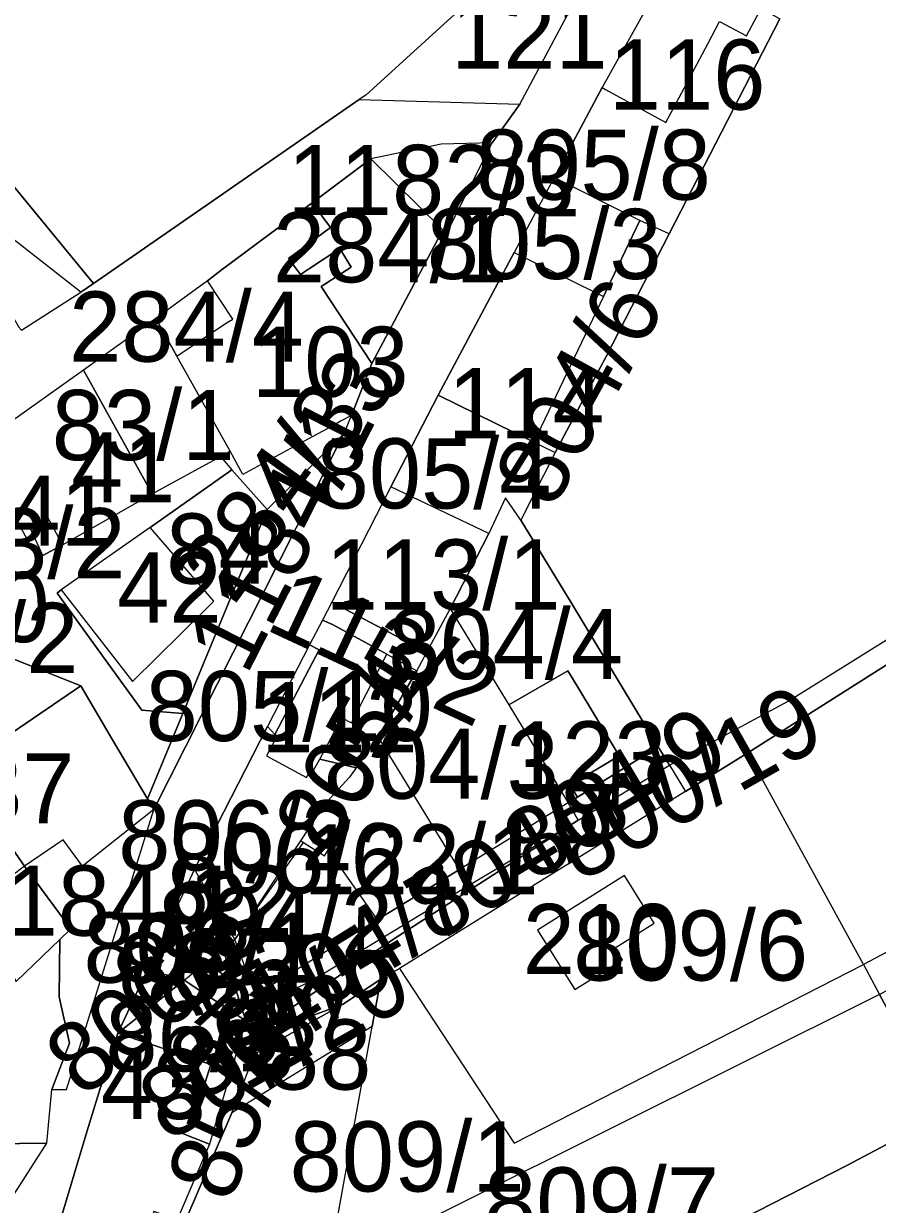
# Model space of a CAD drawing. Extents: x -623250 to -619626, y -1079612 to -1075424.
# Drawn here: x -621368.8 to -621247.2, y -1077081.9 to -1076913.6 of the extents above; entities that cross this region are included whole.
import ezdxf

# ---------------------------------------------------------------- set-up
doc = ezdxf.new("R2010")
doc.units = 0
for name, color, linetype in [('Hranice převzatá (k_ú_Džbánov - vnitřní obvod)', 7, 'Continuous'), ('Hranice šetřená (k_ú_Džbánov - vnitřní obvod)', 7, 'Continuous'), ('Parcela nároku', 7, 'Continuous'), ('Parcelní číslo', 7, 'Continuous')]:
    doc.layers.add(name, color=color, linetype=linetype)

msp = doc.modelspace()

# ---------------------------------------------------------------- linework, layer by layer
at = {"layer": 'Hranice převzatá (k_ú_Džbánov - vnitřní obvod)'}
msp.add_line((-621276.85, -1076943.57), (-621261.07, -1076912.95), dxfattribs=at)
at = {"layer": 'Hranice šetřená (k_ú_Džbánov - vnitřní obvod)'}
for points in [[(-621276.85, -1076943.57), (-621285.83, -1076961.08), (-621293.09, -1076974.77), (-621297.99, -1076984.39), (-621290.77, -1076996.21), (-621278.41, -1077016.7), (-621276.8, -1077019.33), (-621274.52, -1077023.06), (-621265.63, -1077017.55)], [(-621265.63, -1077017.55), (-621210.28, -1076982.43), (-621187.76, -1076968.09), (-621182.95, -1076968.95), (-621180.28, -1076982.79), (-621175.85, -1077005.66), (-621175.29, -1077008.58), (-621176.78, -1077009.37), (-621249.17, -1077047.73), (-621246.87, -1077052), (-621237.68, -1077069.07), (-621251.52, -1077076.38), (-621294, -1077098.09)]]:
    msp.add_lwpolyline(points, dxfattribs=at)
at = {"layer": 'Parcela nároku'}
for points in [[(-621388.91, -1076914.43), (-621261.7, -1076848.72), (-621265.74, -1076862.26), (-621268.27, -1076865.58), (-621302.1, -1076905.64), (-621306.34, -1076911.31), (-621320.09, -1076923.81), (-621321.03, -1076924.46), (-621358.9, -1076950.67), (-621371.51, -1076935.3)], [(-621263.97, -1076911.91), (-621270.87, -1076908.16), (-621270.64, -1076907.72), (-621275.91, -1076904.88), (-621276.33, -1076904.65), (-621286.38, -1076922.74), (-621285.9, -1076923.02), (-621277.33, -1076927.74), (-621271.34, -1076916.49), (-621269.65, -1076913.33), (-621265.81, -1076915.39)], [(-621320.09, -1076923.81), (-621321.03, -1076924.46), (-621298.1, -1076925.1), (-621290.94, -1076911.65), (-621292.93, -1076910.56), (-621301.18, -1076906.02), (-621302.1, -1076905.64), (-621306.34, -1076911.31)], [(-621293.22, -1076935.57), (-621286.38, -1076922.74), (-621285.9, -1076923.02), (-621277.33, -1076927.74), (-621271.34, -1076916.49), (-621269.65, -1076913.33), (-621265.81, -1076915.39), (-621263.97, -1076911.91), (-621270.87, -1076908.16), (-621270.64, -1076907.72), (-621265.64, -1076910.36), (-621261.07, -1076912.95), (-621276.85, -1076943.57), (-621281.03, -1076941.69)], [(-621400.8, -1076920.49), (-621388.91, -1076914.43), (-621371.51, -1076935.3), (-621358.9, -1076950.67), (-621360.7, -1076951.91), (-621382.24, -1076935.03)], [(-621302.09, -1076930.63), (-621309.35, -1076930.8), (-621319.37, -1076932.91), (-621309.08, -1076943.03), (-621308.57, -1076943.53)], [(-621319.37, -1076932.91), (-621309.08, -1076943.03), (-621319.23, -1076962.06), (-621326.44, -1076951.11), (-621322.14, -1076948.34), (-621323.79, -1076945.68), (-621328.08, -1076948.53), (-621329.38, -1076949.38), (-621331.07, -1076947.1), (-621325.12, -1076942.7), (-621327.72, -1076939.17)], [(-621379.74, -1076967.98), (-621381.79, -1076964.51), (-621383.13, -1076965.27), (-621387.85, -1076967.95), (-621390.29, -1076963.84), (-621392.46, -1076965.01), (-621396.79, -1076957.69), (-621394.63, -1076956.52), (-621397.27, -1076952.05), (-621392.43, -1076949.18), (-621385.65, -1076945.85), (-621384.21, -1076945.15), (-621378.08, -1076942.14), (-621369.5, -1076956.9), (-621369.14, -1076957.33), (-621360.7, -1076951.91), (-621382.24, -1076935.03), (-621407.3, -1076948.06), (-621406.33, -1076956.01), (-621402.48, -1076963.6), (-621399.42, -1076969.63), (-621397.07, -1076974.26)], [(-621281.03, -1076941.69), (-621293.22, -1076935.57), (-621298.92, -1076946.24), (-621290.81, -1076950.26), (-621286.98, -1076952.16), (-621286.21, -1076952.54)], [(-621339.91, -1076956.28), (-621339.04, -1076955.74), (-621342.62, -1076950.28), (-621340.68, -1076948.78), (-621333.65, -1076943.52), (-621327.72, -1076939.17), (-621325.12, -1076942.7), (-621331.07, -1076947.1), (-621329.38, -1076949.38), (-621328.08, -1076948.53), (-621323.79, -1076945.68), (-621322.14, -1076948.34), (-621326.44, -1076951.11), (-621319.23, -1076962.06), (-621322.12, -1076969.47), (-621323.57, -1076970.26), (-621324.89, -1076970.98), (-621330.27, -1076973.91), (-621337.59, -1076977.91), (-621339.39, -1076974.58), (-621346.99, -1076961.02)], [(-621276.85, -1076943.57), (-621281.03, -1076941.69), (-621286.21, -1076952.54), (-621296.11, -1076973.28), (-621293.09, -1076974.77), (-621285.83, -1076961.08)], [(-621290.81, -1076950.26), (-621286.98, -1076952.16), (-621286.21, -1076952.54), (-621296.11, -1076973.28), (-621309.78, -1076966.57), (-621298.92, -1076946.24)], [(-621342.62, -1076950.28), (-621350.01, -1076955.67), (-621346.99, -1076961.02), (-621339.91, -1076956.28), (-621339.04, -1076955.74)], [(-621346.99, -1076961.02), (-621350.01, -1076955.67), (-621360.3, -1076963.02), (-621359.65, -1076964.2), (-621350.51, -1076980.67), (-621340.76, -1076975.33), (-621339.39, -1076974.58)], [(-621359.65, -1076964.2), (-621360.3, -1076963.02), (-621374.01, -1076972.77), (-621374.75, -1076973.9), (-621375.15, -1076974.51), (-621366.89, -1076989.84), (-621366.1, -1076989.42), (-621367.97, -1076985.39), (-621365.43, -1076983.95), (-621363.29, -1076987.92), (-621350.51, -1076980.67)], [(-621316.13, -1077044.13), (-621289.81, -1077027.14), (-621276.8, -1077019.33), (-621259.89, -1077010.22), (-621184.11, -1076962.92), (-621183.61, -1076965.53), (-621187.76, -1076968.09), (-621210.28, -1076982.43), (-621265.63, -1077017.55), (-621315.29, -1077048.32), (-621317.95, -1077049.84), (-621323.41, -1077053.43), (-621328.79, -1077055.44), (-621331.46, -1077056.09), (-621334.27, -1077056.32)], [(-621309.78, -1076966.57), (-621296.11, -1076973.28), (-621293.09, -1076974.77), (-621297.99, -1076984.39), (-621300.15, -1076981.22), (-621302.56, -1076986.31), (-621316.49, -1076979.64)], [(-621180.28, -1076982.79), (-621175.85, -1077005.66), (-621175.29, -1077008.58), (-621176.78, -1077009.37), (-621249.17, -1077047.73), (-621265.63, -1077017.55), (-621210.28, -1076982.43), (-621187.76, -1076968.09)], [(-621337.59, -1076977.91), (-621339.39, -1076974.58), (-621340.76, -1076975.33), (-621339.16, -1076977.21), (-621334.11, -1076982.88), (-621323.26, -1076972.15), (-621322.86, -1076971.35), (-621322.12, -1076969.47), (-621323.57, -1076970.26), (-621324.89, -1076970.98), (-621330.27, -1076973.91)], [(-621346.15, -1077011.97), (-621334.11, -1076982.88), (-621323.26, -1076972.15), (-621350.29, -1077025.63), (-621351.18, -1077024.13)], [(-621356.81, -1077002.91), (-621353.34, -1077007.39), (-621346.41, -1077000.56), (-621341.74, -1076995.95), (-621350.8, -1076985.46), (-621339.16, -1076977.21), (-621334.11, -1076982.88), (-621346.15, -1077011.97), (-621351.97, -1077011.5), (-621364.08, -1076994.82), (-621363.47, -1076994.33)], [(-621302.56, -1076986.31), (-621316.49, -1076979.64), (-621324.93, -1076996.07), (-621311.36, -1077003.21), (-621308.04, -1076997.05)], [(-621302.56, -1076986.31), (-621308.04, -1076997.05), (-621299.71, -1077010.73), (-621291.29, -1077005.87), (-621290.67, -1077006.89), (-621287.93, -1077011.41), (-621283.96, -1077017.97), (-621290.94, -1077022.16), (-621289.92, -1077023.88), (-621278.41, -1077016.7), (-621290.77, -1076996.21), (-621297.99, -1076984.39), (-621300.15, -1076981.22)], [(-621367.97, -1076985.39), (-621365.43, -1076983.95), (-621363.29, -1076987.92), (-621366.1, -1076989.42)], [(-621341.74, -1076995.95), (-621350.8, -1076985.46), (-621356.16, -1076989.21), (-621363.47, -1076994.33), (-621356.81, -1077002.91), (-621353.34, -1077007.39), (-621346.41, -1077000.56)], [(-621413.47, -1076991.52), (-621407.45, -1076988.85), (-621401, -1076993.07), (-621390.43, -1076997.35), (-621376.71, -1077001.63), (-621371.16, -1077003.85), (-621360.7, -1077008.03), (-621378.27, -1077020), (-621368.71, -1077033.73), (-621371.16, -1077035.61), (-621399.89, -1076998.58)], [(-621399.89, -1076998.58), (-621413.47, -1076991.52), (-621418.63, -1076993.81), (-621407.49, -1077016.65), (-621409.18, -1077017.58), (-621391.08, -1077055.64), (-621389.91, -1077057.9), (-621374.82, -1077088.56), (-621373.89, -1077088.8), (-621372.14, -1077089.23), (-621370.85, -1077081.53), (-621365.54, -1077073.2), (-621377.33, -1077073.32), (-621386.59, -1077059.95), (-621391.92, -1077049.63), (-621375.37, -1077039.83), (-621369.9, -1077050.16), (-621363.69, -1077044.16), (-621362.12, -1077042.64), (-621368.71, -1077033.73), (-621371.16, -1077035.61)], [(-621324.93, -1076996.07), (-621326.25, -1076998.64), (-621324.83, -1076999.28), (-621317.08, -1077003.52), (-621312.79, -1077005.87), (-621311.36, -1077003.21)], [(-621299.71, -1077010.73), (-621291.22, -1077024.69), (-621306.72, -1077034.21), (-621318.33, -1077015.29), (-621312.79, -1077005.87), (-621311.36, -1077003.21), (-621308.04, -1076997.05)], [(-621327.67, -1077004.7), (-621333.04, -1077014.97), (-621332.72, -1077015.14), (-621334.24, -1077018), (-621328.51, -1077021.1), (-621328.06, -1077020.3), (-621327.76, -1077020.45), (-621326.64, -1077018.46), (-621323.5, -1077012.56), (-621322.13, -1077013.28), (-621318.92, -1077007.07), (-621317.08, -1077003.52), (-621324.83, -1076999.28), (-621326.25, -1076998.64), (-621328.09, -1077002.19), (-621326.74, -1077002.9)], [(-621328.09, -1077002.19), (-621334.09, -1077013.79), (-621333.04, -1077014.97), (-621327.67, -1077004.7), (-621326.74, -1077002.9)], [(-621323.5, -1077012.56), (-621322.13, -1077013.28), (-621318.92, -1077007.07), (-621317.08, -1077003.52), (-621312.79, -1077005.87), (-621318.33, -1077015.29), (-621321.45, -1077019.71), (-621326.64, -1077018.46)], [(-621283.96, -1077017.97), (-621287.93, -1077011.41), (-621290.67, -1077006.89), (-621291.29, -1077005.87), (-621299.71, -1077010.73), (-621291.22, -1077024.69), (-621289.92, -1077023.88), (-621290.94, -1077022.16)], [(-621378.27, -1077020), (-621360.7, -1077008.03), (-621356.16, -1077015.71), (-621351.18, -1077024.13), (-621350.29, -1077025.63), (-621360.47, -1077033.73), (-621363.22, -1077029.96), (-621368.71, -1077033.73)], [(-621176.78, -1077009.37), (-621249.17, -1077047.73), (-621246.87, -1077052), (-621187.87, -1077019.16), (-621177.76, -1077013.49)], [(-621326.64, -1077018.46), (-621321.45, -1077019.71), (-621322.39, -1077021.04), (-621325.99, -1077024.98), (-621329.39, -1077030.08), (-621338.72, -1077044.17), (-621344.48, -1077034.16), (-621334.09, -1077013.79), (-621333.04, -1077014.97), (-621332.72, -1077015.14), (-621334.24, -1077018), (-621328.51, -1077021.1), (-621328.06, -1077020.3), (-621327.76, -1077020.45)], [(-621318.33, -1077015.29), (-621321.45, -1077019.71), (-621322.39, -1077021.04), (-621325.99, -1077024.98), (-621329.39, -1077030.08), (-621328.96, -1077030.35), (-621325.98, -1077032.25), (-621325.43, -1077031.43), (-621318.47, -1077041.37), (-621306.72, -1077034.21)], [(-621265.63, -1077017.55), (-621315.29, -1077048.32), (-621298.91, -1077073.21), (-621249.17, -1077047.73)], [(-621289.92, -1077023.88), (-621291.22, -1077024.69), (-621289.81, -1077027.14), (-621276.8, -1077019.33), (-621278.41, -1077016.7)], [(-621291.22, -1077024.69), (-621306.72, -1077034.21), (-621305.79, -1077036.68), (-621289.81, -1077027.14)], [(-621362.12, -1077042.64), (-621363.69, -1077044.16), (-621363.76, -1077052.36), (-621362.28, -1077058.96), (-621364.82, -1077065.54), (-621362.74, -1077065.56), (-621350.29, -1077025.63), (-621360.47, -1077033.73), (-621363.22, -1077029.96), (-621368.71, -1077033.73)], [(-621305.79, -1077036.68), (-621289.81, -1077027.14), (-621316.13, -1077044.13), (-621334.27, -1077056.32), (-621335.73, -1077052.34), (-621335.81, -1077052.11), (-621331.49, -1077051.5), (-621329.39, -1077050.8), (-621327.42, -1077049.83)], [(-621329.39, -1077030.08), (-621338.72, -1077044.17), (-621328.96, -1077030.35)], [(-621328.96, -1077030.35), (-621325.98, -1077032.25), (-621325.43, -1077031.43), (-621318.47, -1077041.37), (-621335.81, -1077052.11), (-621338.72, -1077044.17)], [(-621338.72, -1077044.17), (-621344.48, -1077034.16), (-621351.33, -1077048.78), (-621346.81, -1077049.41), (-621345.97, -1077049.96), (-621342.62, -1077047.26), (-621340.44, -1077045.54)], [(-621306.72, -1077034.21), (-621318.47, -1077041.37), (-621335.81, -1077052.11), (-621331.49, -1077051.5), (-621329.39, -1077050.8), (-621327.42, -1077049.83), (-621305.79, -1077036.68)], [(-621295.61, -1077042.83), (-621290.29, -1077051.31), (-621283.48, -1077047.08), (-621284.52, -1077045.37), (-621278.97, -1077041.85), (-621283.22, -1077035.04)], [(-621283.22, -1077035.04), (-621295.61, -1077042.83), (-621290.29, -1077051.31), (-621283.48, -1077047.08), (-621284.52, -1077045.37), (-621278.97, -1077041.85)], [(-621362.28, -1077058.96), (-621363.76, -1077052.36), (-621363.69, -1077044.16), (-621369.9, -1077050.16), (-621375.37, -1077039.83), (-621391.92, -1077049.63), (-621386.59, -1077059.95), (-621377.33, -1077073.32), (-621365.54, -1077073.2), (-621364.82, -1077065.54)], [(-621335.81, -1077052.11), (-621338.72, -1077044.17), (-621340.44, -1077045.54), (-621338.86, -1077050.46), (-621337.53, -1077051.55), (-621336.66, -1077052.06), (-621335.73, -1077052.34)], [(-621342.62, -1077047.26), (-621340.44, -1077045.54), (-621338.86, -1077050.46), (-621341.91, -1077047.96)], [(-621341.91, -1077047.96), (-621338.86, -1077050.46), (-621337.16, -1077055.74), (-621345.97, -1077049.96), (-621342.62, -1077047.26)], [(-621251.52, -1077076.38), (-621237.68, -1077069.07), (-621195.75, -1077048.12), (-621213.24, -1077089.84), (-621248.89, -1077106.94), (-621280.89, -1077123.84), (-621283.01, -1077121.21), (-621310.49, -1077133.23), (-621335.24, -1077144.05), (-621334, -1077138.41), (-621331.64, -1077139.45), (-621320.19, -1077112.66), (-621294, -1077098.09)], [(-621298.91, -1077073.21), (-621249.17, -1077047.73), (-621246.87, -1077052), (-621325.45, -1077091.18), (-621319.17, -1077056.56), (-621317.95, -1077049.84), (-621315.29, -1077048.32)], [(-621346.81, -1077049.41), (-621345.97, -1077049.96), (-621355.43, -1077057.52), (-621351.33, -1077048.78)], [(-621345.97, -1077049.96), (-621337.16, -1077055.74), (-621342.37, -1077073.32), (-621349.19, -1077070.65), (-621348.45, -1077068.57), (-621344.65, -1077069.83), (-621342.15, -1077061.97), (-621355.43, -1077057.52)], [(-621323.41, -1077053.43), (-621317.95, -1077049.84), (-621319.17, -1077056.56), (-621339.15, -1077068.87), (-621335.88, -1077060.47)], [(-621336.66, -1077052.06), (-621335.73, -1077052.34), (-621334.27, -1077056.32), (-621337.16, -1077055.74), (-621338.86, -1077050.46), (-621337.53, -1077051.55)], [(-621328.79, -1077055.44), (-621323.41, -1077053.43), (-621335.88, -1077060.47), (-621334.27, -1077056.32), (-621331.46, -1077056.09)], [(-621246.87, -1077052), (-621325.45, -1077091.18), (-621328.14, -1077111.81), (-621329.46, -1077117.82), (-621320.19, -1077112.66), (-621294, -1077098.09), (-621251.52, -1077076.38), (-621237.68, -1077069.07)], [(-621339.15, -1077068.87), (-621345.88, -1077084.47), (-621353.66, -1077102.52), (-621334.97, -1077109.37), (-621328.14, -1077111.81), (-621325.45, -1077091.18), (-621319.17, -1077056.56)], [(-621337.16, -1077055.74), (-621342.37, -1077073.32), (-621346.97, -1077084.1), (-621345.88, -1077084.47), (-621339.15, -1077068.87), (-621335.88, -1077060.47), (-621334.27, -1077056.32)], [(-621359.83, -1077071.59), (-621357.91, -1077065.42), (-621355.43, -1077057.52), (-621342.15, -1077061.97), (-621344.65, -1077069.83), (-621348.45, -1077068.57), (-621349.19, -1077070.65), (-621342.37, -1077073.32), (-621346.97, -1077084.1), (-621350.29, -1077082.92), (-621352.02, -1077087.69), (-621362.11, -1077084.13), (-621363.46, -1077083.65)]]:
    msp.add_lwpolyline(points, close=True, dxfattribs=at)
for points in [[(-621261.07, -1076912.95), (-621276.85, -1076943.57), (-621285.83, -1076961.08), (-621293.09, -1076974.77), (-621297.99, -1076984.39), (-621290.77, -1076996.21), (-621278.41, -1077016.7), (-621276.8, -1077019.33), (-621259.89, -1077010.22), (-621184.11, -1076962.92), (-621136.45, -1076933.16), (-621132.46, -1076928.18), (-621119.89, -1076900.74)], [(-621276.33, -1076904.65), (-621286.38, -1076922.74), (-621293.22, -1076935.57), (-621298.92, -1076946.24), (-621309.78, -1076966.57), (-621316.49, -1076979.64), (-621324.93, -1076996.07), (-621326.25, -1076998.64), (-621328.09, -1077002.19), (-621334.09, -1077013.79), (-621344.48, -1077034.16), (-621351.33, -1077048.78), (-621355.43, -1077057.52), (-621357.91, -1077065.42), (-621359.83, -1077071.59), (-621363.46, -1077083.65), (-621362.11, -1077084.13), (-621362.86, -1077089.41), (-621364.18, -1077098.66), (-621380.94, -1077143.37), (-621383.09, -1077146.69), (-621409.34, -1077186.93), (-621429.78, -1077218.32)], [(-621432.3, -1077203.73), (-621404.2, -1077162.3), (-621400.21, -1077156.98), (-621391.61, -1077145.5), (-621390.49, -1077143.5), (-621383.83, -1077133.32), (-621376.62, -1077119.92), (-621377.43, -1077118.16), (-621374.04, -1077099.65), (-621372.14, -1077089.23), (-621370.85, -1077081.53), (-621365.54, -1077073.2), (-621364.82, -1077065.54), (-621362.74, -1077065.56), (-621350.29, -1077025.63), (-621323.26, -1076972.15), (-621322.86, -1076971.35), (-621322.12, -1076969.47), (-621319.23, -1076962.06), (-621309.08, -1076943.03), (-621308.57, -1076943.53), (-621302.09, -1076930.63), (-621298.1, -1076925.1), (-621290.94, -1076911.65)], [(-621369.14, -1076957.33), (-621360.7, -1076951.91), (-621358.9, -1076950.67), (-621321.03, -1076924.46), (-621298.1, -1076925.1), (-621302.09, -1076930.63), (-621309.35, -1076930.8), (-621319.37, -1076932.91), (-621327.72, -1076939.17), (-621333.65, -1076943.52), (-621340.68, -1076948.78), (-621342.62, -1076950.28), (-621350.01, -1076955.67), (-621360.3, -1076963.02), (-621374.01, -1076972.77)], [(-621375.15, -1076974.51), (-621366.89, -1076989.84), (-621366.1, -1076989.42), (-621363.29, -1076987.92), (-621350.51, -1076980.67), (-621340.76, -1076975.33), (-621339.16, -1076977.21), (-621350.8, -1076985.46), (-621356.16, -1076989.21), (-621363.47, -1076994.33), (-621364.08, -1076994.82), (-621351.97, -1077011.5), (-621346.15, -1077011.97), (-621351.18, -1077024.13), (-621356.16, -1077015.71), (-621360.7, -1077008.03), (-621371.16, -1077003.85)]]:
    msp.add_lwpolyline(points, dxfattribs=at)

# ---------------------------------------------------------------- texts
at = {"layer": 'Parcelní číslo'}
for s, p in [('121', (-621307.91, -1076920.03)), ('116', (-621285.44, -1076925.89)), ('805/8', (-621304.36, -1076938.73)), ('1182/3', (-621331.21, -1076940.91)), ('284/1', (-621333.31, -1076950.5)), ('805/3', (-621311.38, -1076950.03)), ('284/4', (-621362.36, -1076961.81)), ('103', (-621336.29, -1076966.83)), ('114', (-621308.36, -1076972.73)), ('83/1', (-621364.82, -1076975.84)), ('41', (-621362.08, -1076981.87)), ('805/4', (-621327.07, -1076982.74)), ('1141', (-621385.91, -1076988.04)), ('83/2', (-621380.34, -1076992.69)), ('84', (-621348.52, -1076993.45)), ('113/1', (-621325.8, -1076997.15)), ('42', (-621355.5, -1076998.99)), ('1230', (-621394.88, -1077001.79)), ('77/2', (-621387.06, -1077006.18)), ('804/4', (-621316.89, -1077007.05)), ('805/10', (-621351.45, -1077015.88)), ('112', (-621334.97, -1077017.47)), ('123', (-621299.53, -1077023.07)), ('804/3', (-621326.05, -1077024.11)), ('37', (-621376.47, -1077027.62)), ('806/2', (-621355.36, -1077034.33)), ('806/6', (-621348.26, -1077037.59)), ('122/1', (-621328.93, -1077037.74)), ('1184/12', (-621378.83, -1077043.62)), ('804/2', (-621349.65, -1077046.77)), ('806/1', (-621360.31, -1077050.32)), ('210', (-621297.71, -1077049.1)), ('809/6', (-621290.51, -1077050.02)), ('86/3', (-621355.36, -1077053.12)), ('86/1', (-621357.19, -1077062.96)), ('88', (-621334.16, -1077065.56)), ('43', (-621357.83, -1077069.75)), ('809/1', (-621330.92, -1077080.09)), ('809/7', (-621303.22, -1077086.65))]:
    msp.add_text(s, height=10, dxfattribs=at).set_placement(p)
for s, rotation, p in [('804/6', 61.1384, (-621293.44, -1076983.07)), ('1184/13', 63.1093, (-621337.07, -1077006.69)), ('284/3', 54.092, (-621338.89, -1076996.69)), ('113/2', 334.9688, (-621334.63, -1076999.88)), ('805/5', 60.6532, (-621324.9, -1077032.64)), ('800/19', 29.4652, (-621289.66, -1077036.18)), ('804/9', 30.8756, (-621296.37, -1077036.16)), ('804/8', 30.9999, (-621310.32, -1077044.85)), ('804/7', 30.3595, (-621332.81, -1077058.09)), ('85/5', 290.1278, (-621348.58, -1077036.39)), ('806/7', 38.6319, (-621360.46, -1077066.91)), ('86/2', 326.7377, (-621356.93, -1077047.68)), ('85/4', 299.1278, (-621348.24, -1077044.18)), ('804/5', 31.9835, (-621343.78, -1077067.61)), ('800/20', 29.4652, (-621348.5, -1077073.16)), ('85/3', 68.7298, (-621339.42, -1077081.96))]:
    msp.add_text(s, height=10, rotation=rotation, dxfattribs=at).set_placement(p)

doc.saveas('drawing.dxf')
